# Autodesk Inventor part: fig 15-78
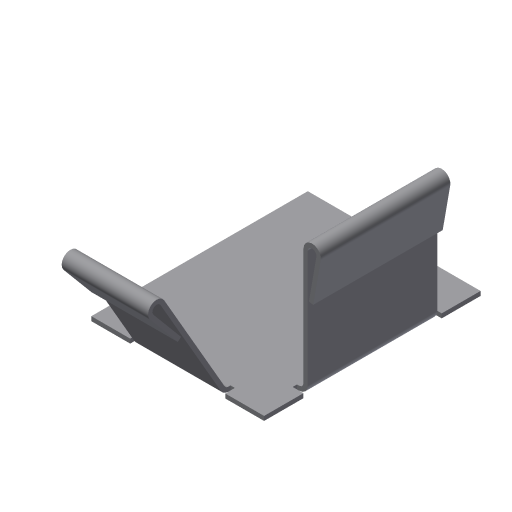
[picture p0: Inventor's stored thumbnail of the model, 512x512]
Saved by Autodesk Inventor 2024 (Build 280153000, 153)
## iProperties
Shininess: 77.0
Angle Display Precision: 2
Document Length Units: 11269
Document Angle Units: 11279
Document Time Units: 11290
Document Mass Units: 11283
Document Length Units Precision: 3
Document Angle Units Precision: 2
Compacted: True
Created: 2002-04
Part Number: fig 15-78
Document SubType Name: Sheet Metal
Density: 1 g/cm^3
Sheet Metal Rule: Default
Material: Generic
Appearance: Default
Density: 0.0
Volumn: 0.0
Area: 0.0
PropertySet Name: Model Information
Control State: 0
Master: False
Checked Out: False
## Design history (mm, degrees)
node "Face1"
  sketch "Sketch1"
    geometry: L1 (-17.882, 11.882)-(2.118, 11.882); L2 (2.118, 11.882)-(2.118, -13.176); L3 (2.118, -13.176)-(-17.882, -13.176); L4 (-17.882, -13.176)-(-17.882, 11.882)
    constraints: 8 end point, 2 parallel, 1 horizontal, 1 perpendicular
    dimensions: "d17" = 20 distance of L2.end L3.end
node "Flange2"
node "Flange3"
feature "Hem8" dims "d82" = 0.5 (= BendReliefWidth), "d83" = 0.25 (= BendReliefDepth), "d84" = 1 (= MinimumRemnant), "d85" = 0.5 (= BendRadius), "d96" = 190 deg, "d97" = 0.5 (= BendRadius), "d98" = 0.5 (= d97), "d102" = 0.5 (= Thickness), "SeamGap" = 0.01
feature "Hem9" dims "d89" = 0.5 (= BendReliefWidth), "d90" = 0.25 (= BendReliefDepth), "d91" = 1 (= MinimumRemnant), "d92" = 0.5 (= BendRadius), "d99" = 190 deg, "d100" = 0.5 (= BendRadius), "d101" = 0.5 (= d100), "d102" = 0.5 (= Thickness), "SeamGap" = 0.01
body "Solid1"
face "Plate1" dims "d102" = 0.5 (= Thickness)
sketch "Sketch3"
  geometry: L1 (5, 0)-(20, 0); L2 (20, 0)-(20, 15); L3 (20, 15)-(5, 15); L4 (5, 15)-(5, 0)
  constraints: 8 end point
face "Plate3" dims "d6" = 15, "d7" = 90 deg, "d8" = 0.5 (= BendRadius), "d18" = 5, "d19" = 15, "d102" = 0.5 (= Thickness), "MinimumRemnant" = 1 (= 2 x Thickness), "BendReliefWidth" = 0.5 (= Thickness)
bend "Bend2" dims "d6" = 15, "d7" = 90 deg, "d8" = 0.5 (= BendRadius), "d56" = 0.5 (= BendReliefWidth), "d57" = 0.25 (= BendReliefDepth), "d58" = 1 (= MinimumRemnant), "d102" = 0.5 (= Thickness), "SeamGap" = 0.01, "MinimumRemnant" = 1 (= 2 x Thickness), "BendReliefWidth" = 0.5 (= Thickness), "TransitionRadius" = 0.5 (= BendRadius)
sketch "Sketch6"
  geometry: L1 (15, 0)-(5, 0); L2 (5, 0)-(5, 15); L3 (5, 15)-(15, 15); L4 (15, 15)-(15, 0)
  constraints: 8 end point
face "Plate4" dims "d20" = 5, "d21" = 10, "d23" = 15, "d24" = 60 deg, "d25" = 0.5 (= BendRadius), "d102" = 0.5 (= Thickness), "MinimumRemnant" = 1 (= 2 x Thickness), "BendReliefWidth" = 0.5 (= Thickness)
bend "Bend3" dims "d22" = 0.5 (= BendRadius), "d23" = 15, "d24" = 60 deg, "d25" = 0.5 (= BendRadius), "d59" = 0.5 (= BendReliefWidth), "d60" = 0.25 (= BendReliefDepth), "d61" = 1 (= MinimumRemnant), "d102" = 0.5 (= Thickness), "SeamGap" = 0.01, "MinimumRemnant" = 1 (= 2 x Thickness), "BendReliefWidth" = 0.5 (= Thickness)
sketch "Sketch12"
  geometry: L1 (0.433, 0.25)-(0, 0); L2 (-0.816, -0.571)-(2.395, -4.398); L3 (2.395, -4.398)-(2.012, -4.719); L4 (2.012, -4.719)-(-1.199, -0.893); A1 r 0.5 centre (-0.433, -0.25) between (0, 0) and (-0.816, -0.571); A2 r 1 centre (-0.433, -0.25) between (0.433, 0.25) and (-1.199, -0.893); 2 further points
  constraints: 8 end point, 4 point on circle
sketch "Sketch13"
  geometry: L1 (0.5, 0)-(0, 0); L2 (-0.992, -0.087)-(-0.125, -5.006); L3 (-0.125, -5.006)-(-0.617, -5.093); L4 (-0.617, -5.093)-(-1.485, -0.174); A1 r 0.5 centre (-0.5, 0) between (0, 0) and (-0.992, -0.087); A2 r 1 centre (-0.5, 0) between (0.5, 0) and (-1.485, -0.174); 2 further points
  constraints: 8 end point, 4 point on circle
other parameters: "Thickness" = 0.5, "BendRadius" = 0.5 (= Thickness), "BendReliefDepth" = 0.25 (= 0.5 x Thickness), "CornerReliefSize" = 2 (= 4 x Thickness), "d0" = 0.5 (= BendRadius), "d5" = 0.5 (= BendRadius), "d26" = 0.5 (= BendRadius), "d30" = 0.5 (= BendRadius), "JacobiRadiusSize" = 0.5 (= Thickness), "GapSize" = 0.5 (= Thickness)
